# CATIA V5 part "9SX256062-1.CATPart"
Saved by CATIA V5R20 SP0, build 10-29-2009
Part number: 9SX256062-1
Revision: ANY
Definition: UNKNOWN
Nomenclature: 9SX256062-1
Source: Unknown
Bounding box of the stored display mesh (mm): x -12.5 to 12.5, y -12.31 to 12.31, z 0 to 480
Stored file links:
  C:\Users\Utente\Desktop\IO LAVORO\3D X SITO CF\CUMSA\3D files SX.256062\SX 256062\9SX256062-1.CATPart
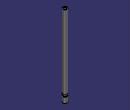
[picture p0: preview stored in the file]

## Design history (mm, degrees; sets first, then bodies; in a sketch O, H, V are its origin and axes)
Body1 "Chaflán7" (main body)
  Solid1: solid without history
